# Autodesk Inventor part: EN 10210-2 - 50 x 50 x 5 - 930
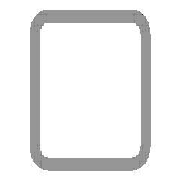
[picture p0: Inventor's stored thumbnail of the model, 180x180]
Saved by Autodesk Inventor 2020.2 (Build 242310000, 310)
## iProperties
IsCustomPart: 1
_CCFamilyMember: 16
_CCFamilyDisplayName: DIN EN 10210-2 (USAS B17.1 quadratisch) - Rohrleitung — In Klammern angegebene Größen wurden aufgehoben
_FrameMemberDoc: Frame Member File
_Version: 15.0.0
_GetPNFromCC: 1
Created: 2019-10
Part Number: EN 10210-2 - 50 x 50 x 5 - 930
Material: Stahl, weich
Description: Rohrleitung
Document SubType Name: Modeling
Standard: DIN
Designer: lutzd
Standard Revision: 2006-07
Standards Organization: DIN
Language: de-DE
Size Designation: 50 x 50 x 5
Categories: <MemberInstance><Categories><Category DisplayName="Profile" InternalName="089c4875-fa83-4c05-b084-43b9cc11f5ed" Mnemonic="GRDR"><CategoryParameter DisplayName="
Stock Number: 50 x 50 x 5
Mass: 6374.61 g
Surface Area: 3165.88 cm^2
Volume: 812.053 cm^3
Density: 7.85 g/cm^3
Appearance: Semi-Polished(8)
G_L: 930,000 mm
G_W: 50,000 mm
G_H: 50,000 mm
Dimensions: 50x50x930 mm
Mass: 6,375 kg
DocNumber: ADSK-014295
Folder: .
+281B1B1F-AD09-41DC-AA94-9C5AFE3D47FB+SCHNITTDETAIL1: Schnittwinkel 90,00 grd
+1372FAE2-8085-4B4E-A435-A1CCBEA902DB+SCHNITTDETAIL2: Schnittwinkel 90,00 grd
VLT_Material: Stahl, weich
Title: Profil-Bauteil
Author: lutzd
Revision Number: -
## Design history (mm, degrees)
node "Startebene"
node "Endebene"
sketch "Skizze"
  geometry: L1 (-25, -17.5)-(-25, 17.5); L2 (-17.5, 25)-(17.5, 25); L3 (25, 17.5)-(25, -17.5); L4 (17.5, -25)-(-17.5, -25); L5 (-15, 20)-(15, 20); L6 (20, 15)-(20, -15); L7 (15, -20)-(-15, -20); L8 (-20, -15)-(-20, 15); L9 (0, 37.175)-(0, -37.175) reference; L10 (-37.175, 0)-(37.175, 0) reference; A1 r 7.5 centre (-17.5, -17.5) between (-25, -17.5) and (-17.5, -25); A2 r 7.5 centre (-17.5, 17.5) between (-17.5, 25) and (-25, 17.5); A3 r 7.5 centre (17.5, 17.5) between (25, 17.5) and (17.5, 25); A4 r 7.5 centre (17.5, -17.5) between (17.5, -25) and (25, -17.5); A5 r 5 centre (-15, -15) between (-20, -15) and (-15, -20); A6 r 5 centre (-15, 15) between (-15, 20) and (-20, 15); A7 r 5 centre (15, 15) between (20, 15) and (15, 20); A8 r 5 centre (15, -15) between (15, -20) and (20, -15)
  constraints: 16 end point, 16 point on circle, 16 tangent, 8 centre point, 6 equal radius, 4 parallel, 2 perpendicular, 2 other
  dimensions: "d7" = 7.5 radius of A1 (= G_IR); "d10" = 50 distance between parallel lines of L2 L4 (= G_H); "d11" = 50 distance between parallel lines of L1 L3 (= G_W); "d12" = 5 distance between parallel lines of L3 L6 (= G_T); "d15" = 25 distance between parallel lines of L2 L10 (= 0.5 x d10); "d16" = 25 distance between parallel lines of L9 L3 (= 0.5 x d11); "d19" = 5 radius of A5 (= G_T); "d20" = 5 distance between parallel lines of L4 L7 (= G_T)
extrude "Körper" new body sketch "Skizze" stored distance "d3" = 930 (= G_L); taper "d4" = 0 deg
node "Driven Length"
  sketch "Sketch3"
    geometry: L1 (0, 0)-(10, 0) reference
    constraints: 2 end point, 1 horizontal
  workplane "Work Plane3"
  sketch "Sketch4"
    geometry: L1 (-2, 50)-(12, 50) reference; L2 (-2, 980)-(12, 980) reference
    dimensions: "d18" = 930 distance between parallel lines of L1 L2 (derived)
workplane "Arbeitsebene4"
feature "Trennen1"
workplane "Arbeitsebene5"
feature "Trennen2"
body "Solid1"
other parameters: "G_W" = 50 [user parameter; used in 1 equation term], "G_H" = 50 [user parameter; used in 1 equation term], "G_T" = 5 [user parameter; used in 3 equation terms], "G_IR" = 7.5 [user parameter; used in 1 equation term], "G_L" = 930 (= d18) [user parameter; used in 1 equation term], "d17" = 90 deg
